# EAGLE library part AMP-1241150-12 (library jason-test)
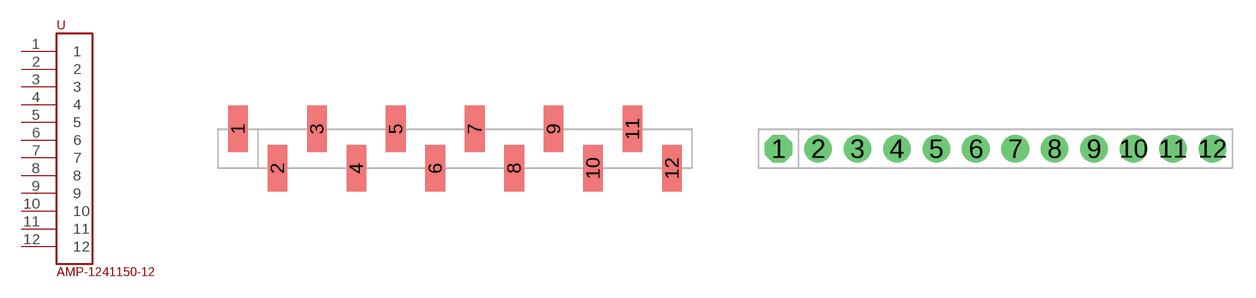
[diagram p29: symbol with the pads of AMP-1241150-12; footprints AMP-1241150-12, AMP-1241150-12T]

Designator prefix -

## AMP-1241150-12SMT  [AMP-1241150-12]
1  1
2  2
3  3
4  4
5  5
6  6
7  7
8  8
9  9
10  10
11  11
12  12

## AMP-1241150-12TH  [AMP-1241150-12T]
Pads as for AMP-1241150-12

## Footprint AMP-1241150-12 (pad centres in mm)
smd 1.27 x 3: 1 -13.97,1.27; 2 -11.43,-1.27; 3 -8.89,1.27; 4 -6.35,-1.27; 5 -3.81,1.27; 6 -1.27,-1.27; 7 1.27,1.27; 8 3.81,-1.27; 9 6.35,1.27; 10 8.89,-1.27; 11 11.43,1.27; 12 13.97,-1.27

## Footprint AMP-1241150-12T (pad centres in mm)
drill 1 pad 1.778 octagon: 1 -13.97,0
drill 1 pad 1.778 round: 2 -11.43,0; 3 -8.89,0; 4 -6.35,0; 5 -3.81,0; 6 -1.27,0; 7 1.27,0; 8 3.81,0; 9 6.35,0; 10 8.89,0; 11 11.43,0; 12 13.97,0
